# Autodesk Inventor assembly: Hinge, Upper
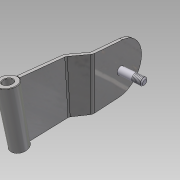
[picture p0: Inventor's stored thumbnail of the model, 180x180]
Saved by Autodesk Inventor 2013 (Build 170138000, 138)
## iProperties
Shininess: 64.0
Length Units: 11269
Angle Units: 11279
Time Units: 11290
Mass Units: 11283
Length Display Precision: 3
Angle Display Precision: 2
Compacted: True
Created: 2004-12
Part Number: Hinge, Upper
Document SubType Name: Assembly
Designer: =<Author>
Manufacturer: Standard
Standards Organization: Custom
Description: =<Part Number>
Mass: 457.379 g
Surface Area: 298.86 cm^2
Volume: 59.0166 cm^3
Density: 7.75 g/cm^3
Density: 0.0
Volumn: 0.0
Area: 0.0
PropertySet Name: Model Information
Control State: 0
Master: False
Checked Out: False
Author: PVitaliy
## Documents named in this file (4)
- Y:\Dropbox\Launch 2013\Eco Material Advisor\Assy, Door\_Data\Assy, Cab\Hinge, Upper.iam
- Y:\Dropbox\Launch 2013\Eco Material Advisor\Assy, Door\_Data\Assy, Cab\Hinge 1.ipt
- Y:\Dropbox\Launch 2013\Eco Material Advisor\Assy, Door\_Data\Assy, Cab\List hinge.ipt
- Y:\Dropbox\Launch 2013\Eco Material Advisor\Assy, Door\_Data\Assy, Cab\PK46.51.13.004.ipt
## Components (3 placed, 3 different names)
1. PK46.51.13.004:1 — Insert:1
2. List hinge:1 — Mate:1, Flush:1, Tangent:1, Insert:1
3. Hinge 1:1 — Flush:1, Tangent:1
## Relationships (4: Mate 1, Flush 1, Tangent 1, Insert 1)
- Mate:1: List hinge:1
- Flush:1: List hinge:1 ↔ Hinge 1:1
- Tangent:1: List hinge:1 ↔ Hinge 1:1
- Insert:1: PK46.51.13.004:1 ↔ List hinge:1
